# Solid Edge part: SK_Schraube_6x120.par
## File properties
Author: fknapp
Template: Iso Metric Part.par
Last saved by: fknapp
Revision: 11
Application: Solid Edge
Username: fknapp
Genauigkeit: 0,990
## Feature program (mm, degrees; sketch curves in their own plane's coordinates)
sketch for "unnamed RevolvedProtrusion 1" plane through (0, 0, 0) normal (1, 0, 0) x-axis (0, 1, 0)
  line (0, -120) -> (3, -114.8038)
  line (3, -114.8038) -> (3, -3.5)
  line (5.5, -1) -> (3, -3.5)
  line (5.5, 0) -> (5.5, -1)
  line (5.5, 0) -> (0, 0)
  dimension (linear) = 5.5
  dimension (linear) = 5.5
revolve "unnamed RevolvedProtrusion 1" add full turn 360 deg about sketch line (0, 0) -> (0, -120)
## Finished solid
Body 1: solid body, 5 faces, 4 edges, 1 vertex.
  Faces by surface: cone 2, cylinder 2, plane 1
  Edges by curve: circle 4
Bounding box of the edges (mm): 11.000 x 11.000 x 114.804, from (-5.5, -5.5, -114.8038) to (5.5, 5.5, 0).
Cylindrical faces by radius (mm): R3 x1, R5.5 x1
Conical faces (half-angle, radius in mm at the cone's reference point): 30 deg R0 x1, 45 deg R3 x1
Planar faces by outward normal: +z 1
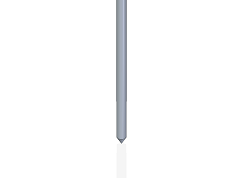
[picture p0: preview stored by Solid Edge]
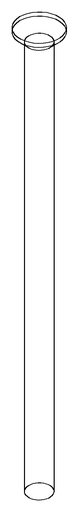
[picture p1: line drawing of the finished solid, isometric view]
